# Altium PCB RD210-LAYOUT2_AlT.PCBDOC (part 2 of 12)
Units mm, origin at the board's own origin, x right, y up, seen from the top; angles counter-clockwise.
Board outline 250 x 123 mm, 4 copper layers (TOP, Mid-Layer 1, Mid-Layer 2, BOTTOM), stack 0.711 mm thick; 1043 components, 659 nets, 2786 pads, 1228 vias.
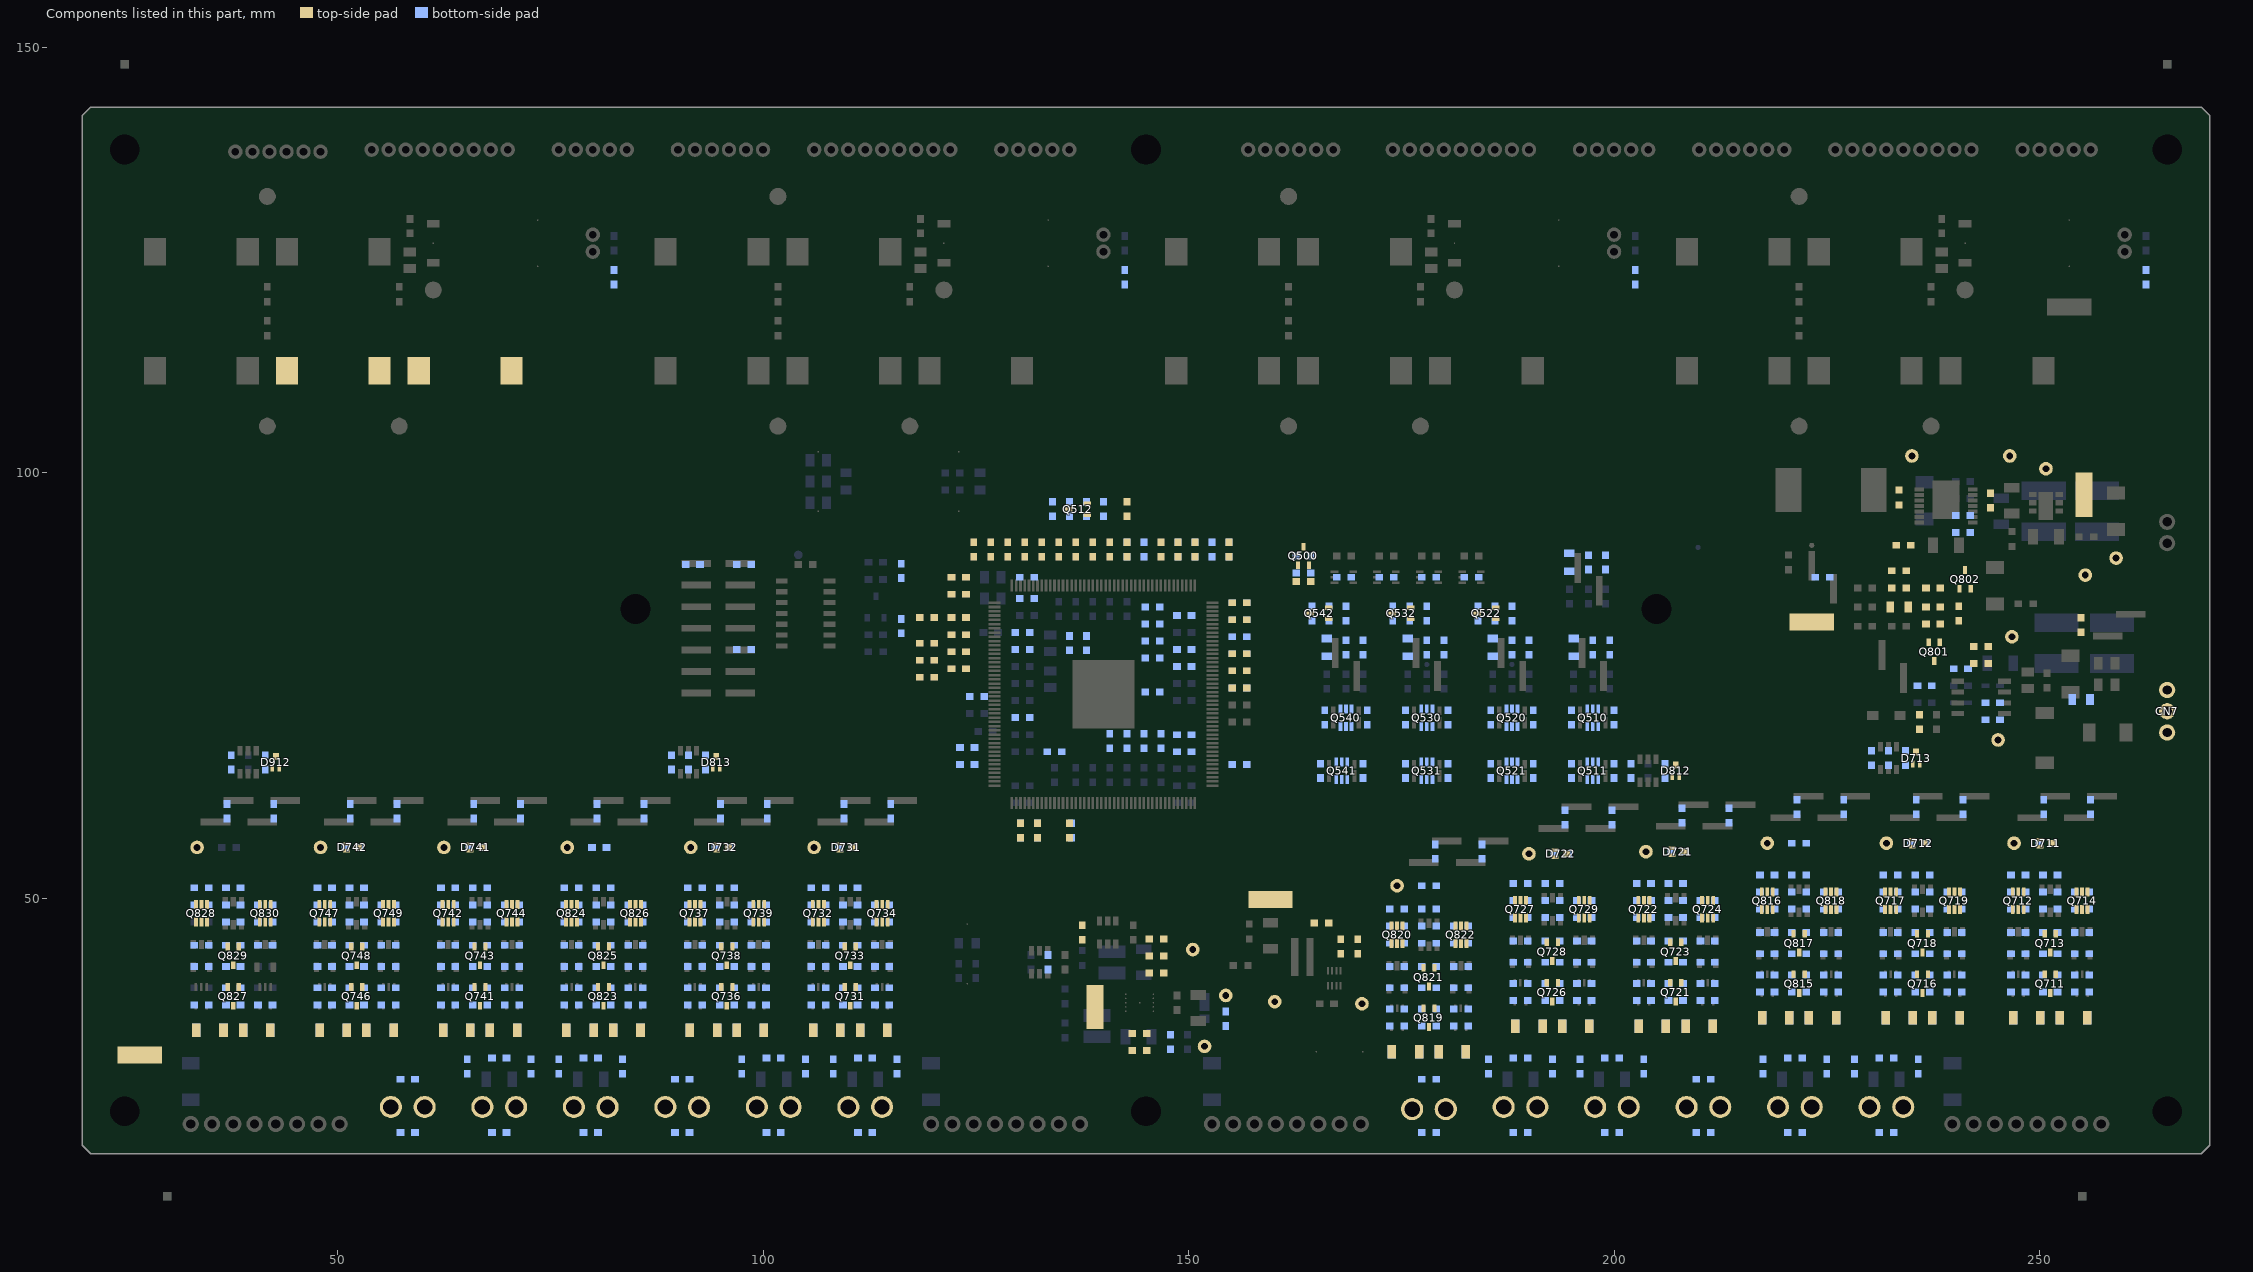
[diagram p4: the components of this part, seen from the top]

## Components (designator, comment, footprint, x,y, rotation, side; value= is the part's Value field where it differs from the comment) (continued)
L820 "S2P_L-12.5x12.1x5.5-PX12.5+18" S2P_L-12.5x12.1x5.5-PX12.5+18 49.5,112 r180 top
L821 "S2P_L-12.5x12.1x5.5-PX12.5+19" S2P_L-12.5x12.1x5.5-PX12.5+19 65,112 r0 top
Q500 "S3P_Q-2.0x1.25x0.9-PX0.65-PY2.1" S3P_Q-2.0x1.25x0.9-PX0.65-PY2.1 163.5,90.25 r0 top
Q510 "_RN1907_" _RN1907_ 197.5,71.25 r0 bottom
Q511 "_RN1907_+1" _RN1907_+1 197.5,65 r0 bottom
Q512 "S3P_Q-2.0x1.25x0.9-PX0.65-PY2.1+6" S3P_Q-2.0x1.25x0.9-PX0.65-PY2.1+6 137,95.75 r90 top
Q520 "_RN1907_+5" _RN1907_+5 188,71.25 r0 bottom
Q521 "_RN1907_+2" _RN1907_+2 188,65 r0 bottom
Q522 "S3P_Q-2.0x1.25x0.9-PX0.65-PY2.1+1" S3P_Q-2.0x1.25x0.9-PX0.65-PY2.1+1 185,83.5 r90 top
Q530 "_RN1907_+7" _RN1907_+7 178,71.25 r0 bottom
Q531 "_RN1907_+6" _RN1907_+6 178,65 r0 bottom
Q532 "S3P_Q-2.0x1.25x0.9-PX0.65-PY2.1+2" S3P_Q-2.0x1.25x0.9-PX0.65-PY2.1+2 175,83.5 r90 top
Q540 "_RN1907_+3" _RN1907_+3 168.5,71.25 r0 bottom
Q541 "_RN1907_+4" _RN1907_+4 168,65 r0 bottom
Q542 "S3P_Q-2.0x1.25x0.9-PX0.65-PY2.1+3" S3P_Q-2.0x1.25x0.9-PX0.65-PY2.1+3 165.375,83.5 r90 top
Q711 "S3P_Q-2.0x1.25x0.9-PX0.65-PY2.1+7" S3P_Q-2.0x1.25x0.9-PX0.65-PY2.1+7 251.25,40 r180 top
Q712 "_RN4907_+22" _RN4907_+22 247.5,49.75 r0 top
Q713 "S3P_Q-2.0x1.25x0.9-PX0.65-PY2.1+8" S3P_Q-2.0x1.25x0.9-PX0.65-PY2.1+8 251.25,44.75 r180 top
Q714 "_RN4907_" _RN4907_ 255,49.75 r0 top
Q716 "S3P_Q-2.0x1.25x0.9-PX0.65-PY2.1+9" S3P_Q-2.0x1.25x0.9-PX0.65-PY2.1+9 236.25,40 r180 top
Q717 "_RN4907_+1" _RN4907_+1 232.5,49.75 r0 top
Q718 "S3P_Q-2.0x1.25x0.9-PX0.65-PY2.1+10" S3P_Q-2.0x1.25x0.9-PX0.65-PY2.1+10 236.25,44.75 r180 top
Q719 "_RN4907_+2" _RN4907_+2 240,49.75 r0 top
Q721 "S3P_Q-2.0x1.25x0.9-PX0.65-PY2.1+11" S3P_Q-2.0x1.25x0.9-PX0.65-PY2.1+11 207.25,39 r180 top
Q722 "_RN4907_+3" _RN4907_+3 203.5,48.75 r0 top
Q723 "S3P_Q-2.0x1.25x0.9-PX0.65-PY2.1+12" S3P_Q-2.0x1.25x0.9-PX0.65-PY2.1+12 207.25,43.75 r180 top
Q724 "_RN4907_+4" _RN4907_+4 211,48.75 r0 top
Q726 "S3P_Q-2.0x1.25x0.9-PX0.65-PY2.1+13" S3P_Q-2.0x1.25x0.9-PX0.65-PY2.1+13 192.75,39 r180 top
Q727 "_RN4907_+5" _RN4907_+5 189,48.75 r0 top
Q728 "S3P_Q-2.0x1.25x0.9-PX0.65-PY2.1+14" S3P_Q-2.0x1.25x0.9-PX0.65-PY2.1+14 192.75,43.75 r180 top
Q729 "_RN4907_+6" _RN4907_+6 196.5,48.75 r0 top
Q731 "S3P_Q-2.0x1.25x0.9-PX0.65-PY2.1+15" S3P_Q-2.0x1.25x0.9-PX0.65-PY2.1+15 110.25,38.5 r180 top
Q732 "_RN4907_+7" _RN4907_+7 106.5,48.25 r0 top
Q733 "S3P_Q-2.0x1.25x0.9-PX0.65-PY2.1+16" S3P_Q-2.0x1.25x0.9-PX0.65-PY2.1+16 110.25,43.25 r180 top
Q734 "_RN4907_+8" _RN4907_+8 114,48.25 r0 top
Q736 "S3P_Q-2.0x1.25x0.9-PX0.65-PY2.1+17" S3P_Q-2.0x1.25x0.9-PX0.65-PY2.1+17 95.75,38.5 r180 top
Q737 "_RN4907_+9" _RN4907_+9 92,48.25 r0 top
Q738 "S3P_Q-2.0x1.25x0.9-PX0.65-PY2.1+18" S3P_Q-2.0x1.25x0.9-PX0.65-PY2.1+18 95.75,43.25 r180 top
Q739 "_RN4907_+10" _RN4907_+10 99.5,48.25 r0 top
Q741 "S3P_Q-2.0x1.25x0.9-PX0.65-PY2.1+19" S3P_Q-2.0x1.25x0.9-PX0.65-PY2.1+19 66.75,38.5 r180 top
Q742 "_RN4907_+11" _RN4907_+11 63,48.25 r0 top
Q743 "S3P_Q-2.0x1.25x0.9-PX0.65-PY2.1+20" S3P_Q-2.0x1.25x0.9-PX0.65-PY2.1+20 66.75,43.25 r180 top
Q744 "_RN4907_+12" _RN4907_+12 70.5,48.25 r0 top
Q746 "S3P_Q-2.0x1.25x0.9-PX0.65-PY2.1+21" S3P_Q-2.0x1.25x0.9-PX0.65-PY2.1+21 52.25,38.5 r180 top
Q747 "_RN4907_+13" _RN4907_+13 48.5,48.25 r0 top
Q748 "S3P_Q-2.0x1.25x0.9-PX0.65-PY2.1+22" S3P_Q-2.0x1.25x0.9-PX0.65-PY2.1+22 52.25,43.25 r180 top
Q749 "_RN4907_+14" _RN4907_+14 56,48.25 r0 top
Q801 "S3P_Q-2.0x1.25x0.9-PX0.65-PY2.1+4" S3P_Q-2.0x1.25x0.9-PX0.65-PY2.1+4 237.625,79 r180 top
Q802 "S3P_Q-2.0x1.25x0.9-PX0.65-PY2.1+5" S3P_Q-2.0x1.25x0.9-PX0.65-PY2.1+5 241.25,87.5 r0 top
Q815 "S3P_Q-2.0x1.25x0.9-PX0.65-PY2.1+23" S3P_Q-2.0x1.25x0.9-PX0.65-PY2.1+23 221.75,40 r180 top
Q816 "_RN4907_+15" _RN4907_+15 218,49.75 r0 top
Q817 "S3P_Q-2.0x1.25x0.9-PX0.65-PY2.1+24" S3P_Q-2.0x1.25x0.9-PX0.65-PY2.1+24 221.75,44.75 r180 top
Q818 "_RN4907_+16" _RN4907_+16 225.5,49.75 r0 top
Q819 "S3P_Q-2.0x1.25x0.9-PX0.65-PY2.1+25" S3P_Q-2.0x1.25x0.9-PX0.65-PY2.1+25 178.25,36 r180 top
Q820 "_RN4907_+23" _RN4907_+23 174.5,45.75 r0 top
Q821 "S3P_Q-2.0x1.25x0.9-PX0.65-PY2.1+26" S3P_Q-2.0x1.25x0.9-PX0.65-PY2.1+26 178.25,40.75 r180 top
Q822 "_RN4907_+17" _RN4907_+17 182,45.75 r0 top
Q823 "S3P_Q-2.0x1.25x0.9-PX0.65-PY2.1+27" S3P_Q-2.0x1.25x0.9-PX0.65-PY2.1+27 81.25,38.5 r180 top
Q824 "_RN4907_+18" _RN4907_+18 77.5,48.25 r0 top
Q825 "S3P_Q-2.0x1.25x0.9-PX0.65-PY2.1+28" S3P_Q-2.0x1.25x0.9-PX0.65-PY2.1+28 81.25,43.25 r180 top
Q826 "_RN4907_+19" _RN4907_+19 85,48.25 r0 top
Q827 "S3P_Q-2.0x1.25x0.9-PX0.65-PY2.1+29" S3P_Q-2.0x1.25x0.9-PX0.65-PY2.1+29 37.75,38.5 r180 top
Q828 "_RN4907_+20" _RN4907_+20 34,48.25 r0 top
Q829 "S3P_Q-2.0x1.25x0.9-PX0.65-PY2.1+30" S3P_Q-2.0x1.25x0.9-PX0.65-PY2.1+30 37.75,43.25 r180 top
Q830 "_RN4907_+21" _RN4907_+21 41.5,48.25 r0 top
R500 "_RS73F1JTTD1002F_+2" _RS73F1JTTD1002F_+2 163.5,90.25 r180 bottom
R501 "_SG73P2ATTD101J_+2" _SG73P2ATTD101J_+2 194.75,89.5 r270 bottom
R502 "_SG73P1JTTD1801F_+2" _SG73P1JTTD1801F_+2 199,89.5 r270 bottom
R503 "_SG73P1JTTD8201F_+2" _SG73P1JTTD8201F_+2 197,89.5 r90 bottom
R504 "_SG73P1JTTD2202F_+5" _SG73P1JTTD2202F_+5 163.5,88.25 r0 bottom
R505 "_SG73P1JTTD2202F_+10" _SG73P1JTTD2202F_+10 163.5,87.25 r180 top
R506 "_RS73G1JTTD1002F_+28" _RS73G1JTTD1002F_+28 144.75,91 r90 bottom
R507 "_RS73G1JTTD1002F_+23" _RS73G1JTTD1002F_+23 134.25,67.25 r180 bottom
R508 "_RS73G1JTTD1002F_+40" _RS73G1JTTD1002F_+40 132.25,58 r90 bottom
R510 "_RS73F1JTTD47R0F_" _RS73F1JTTD47R0F_ 126.75,91 r90 top
R511 "_RS73F1JTTD47R0F_+1" _RS73F1JTTD47R0F_+1 123,85.75 r0 top
R512 "_RS73G1JTTD4701F_+5" _RS73G1JTTD4701F_+5 124.75,91 r90 top
R513 "_RS73G1JTTD4701F_" _RS73G1JTTD4701F_ 119.25,80 r0 top
R514 "_RS73G1JTTD1002F_+27" _RS73G1JTTD1002F_+27 138,80 r270 bottom
R515 "_RS73G1JTTD1002F_+26" _RS73G1JTTD1002F_+26 136,80 r270 bottom
R516 "_RS73G1JTTD4701F_+9" _RS73G1JTTD4701F_+9 200,71.25 r270 bottom
R517 "_RS73G1JTTD1601F_" _RS73G1JTTD1601F_ 195,71.25 r90 bottom
R518 "_RS73G1JTTD1601F_+1" _RS73G1JTTD1601F_+1 200,65 r270 bottom
R519 "_RS73G1JTTD2701F_" _RS73G1JTTD2701F_ 195,65 r90 bottom
R520 "_RS73F1JTTD47R0F_+5" _RS73F1JTTD47R0F_+5 128.75,91 r90 top
R521 "_RS73F1JTTD47R0F_+2" _RS73F1JTTD47R0F_+2 123,83 r0 top
R522 "_RS73G1JTTD4701F_+1" _RS73G1JTTD4701F_+1 123,87.75 r0 top
R523 "_RS73G1JTTD4701F_+2" _RS73G1JTTD4701F_+2 123,79 r0 top
R524 "_RS73G1JTTD1002F_+41" _RS73G1JTTD1002F_+41 130.25,58 r90 bottom
R525 "_RS73G1JTTD1002F_+47" _RS73G1JTTD1002F_+47 146.75,68.5 r270 bottom
R526 "_RS73G1JTTD4701F_+10" _RS73G1JTTD4701F_+10 190.5,71.25 r270 bottom
R527 "_RS73G1JTTD1601F_+2" _RS73G1JTTD1601F_+2 185.5,71.25 r90 bottom
R528 "_RS73G1JTTD1601F_+3" _RS73G1JTTD1601F_+3 190.5,65 r270 bottom
R529 "_RS73G1JTTD2701F_+1" _RS73G1JTTD2701F_+1 185.5,65 r90 bottom
R530 "_RS73F1JTTD47R0F_+6" _RS73F1JTTD47R0F_+6 130.75,91 r90 top
R531 "_RS73F1JTTD47R0F_+4" _RS73F1JTTD47R0F_+4 119.25,83 r0 top
R532 "_RS73G1JTTD4701F_+6" _RS73G1JTTD4701F_+6 138.75,91 r270 top
R533 "_RS73G1JTTD4701F_+3" _RS73G1JTTD4701F_+3 119.25,78 r0 top
R534 "_RS73G1JTTD1002F_" _RS73G1JTTD1002F_ 136,58 r270 top
R535 "_RS73G1JTTD1002F_+1" _RS73G1JTTD1002F_+1 136.25,58 r90 bottom
R536 "_RS73G1JTTD4701F_+11" _RS73G1JTTD4701F_+11 180.5,71.25 r270 bottom
R537 "_RS73G1JTTD1601F_+4" _RS73G1JTTD1601F_+4 175.5,71.25 r90 bottom
R538 "_RS73G1JTTD1601F_+5" _RS73G1JTTD1601F_+5 180.5,65 r270 bottom
R539 "_RS73G1JTTD2701F_+2" _RS73G1JTTD2701F_+2 175.5,65 r90 bottom
R540 "_RS73F1JTTD47R0F_+7" _RS73F1JTTD47R0F_+7 132.75,91 r90 top
R541 "_RS73F1JTTD47R0F_+3" _RS73F1JTTD47R0F_+3 123,81 r0 top
R542 "_RS73G1JTTD4701F_+7" _RS73G1JTTD4701F_+7 140.75,91 r270 top
R543 "_RS73G1JTTD4701F_+4" _RS73G1JTTD4701F_+4 123,77 r0 top
R544 "_RS73G1JTTD1002F_+2" _RS73G1JTTD1002F_+2 156,65.75 r180 bottom
R545 "_RS73G1JTTD1002F_+22" _RS73G1JTTD1002F_+22 149.5,69.25 r180 bottom
R546 "_RS73G1JTTD4701F_+8" _RS73G1JTTD4701F_+8 171,71.25 r270 bottom
R547 "_RS73G1JTTD1601F_+6" _RS73G1JTTD1601F_+6 166,71.25 r90 bottom
R548 "_RS73G1JTTD1601F_+7" _RS73G1JTTD1601F_+7 170.5,65 r270 bottom
R549 "_RS73G1JTTD2701F_+3" _RS73G1JTTD2701F_+3 165.5,65 r90 bottom
R551 "_RS73G1JTTD1002F_+3" _RS73G1JTTD1002F_+3 156,76.75 r180 top
R552 "_RS73G1JTTD1002F_+4" _RS73G1JTTD1002F_+4 156,78.75 r180 top
R553 "_RS73G1JTTD1002F_+5" _RS73G1JTTD1002F_+5 154.75,91 r270 top
R554 "_RS73G1JTTD1002F_+29" _RS73G1JTTD1002F_+29 152.75,91 r90 bottom
R556 "_RS73G1JTTD1002F_+20" _RS73G1JTTD1002F_+20 149.5,77.25 r180 bottom
R557 "_RS73G1JTTD1002F_+18" _RS73G1JTTD1002F_+18 149.5,79.25 r180 bottom
R558 "_RS73G1JTTD1002F_+30" _RS73G1JTTD1002F_+30 154.75,91 r90 bottom
R559 "_RS73G1JTTD1002F_+31" _RS73G1JTTD1002F_+31 150.75,91 r270 top
R562 "_RS73F1JTTD1002F_+8" _RS73F1JTTD1002F_+8 262.5,123 r270 bottom
R563 "_RS73G1JTTD4701F_+14" _RS73G1JTTD4701F_+14 134.75,91 r270 top
R564 "_SG73P2ATTD101J_" _SG73P2ATTD101J_ 195.25,79.5 r270 bottom
R565 "_SG73P1JTTD1801F_" _SG73P1JTTD1801F_ 199.5,79.5 r270 bottom
R566 "_SG73P1JTTD8201F_" _SG73P1JTTD8201F_ 197.5,79.5 r90 bottom
R567 "_SG73P1JTTD2202F_+1" _SG73P1JTTD2202F_+1 140,95.75 r90 bottom
R568 "_SG73P1JTTD2202F_+2" _SG73P1JTTD2202F_+2 138,95.75 r90 bottom
R569 "_RS73F1JTTD1002F_" _RS73F1JTTD1002F_ 136,95.75 r270 bottom
R572 "_RS73F1JTTD1002F_+5" _RS73F1JTTD1002F_+5 202.5,123 r270 bottom
R573 "_RS73G1JTTD4701F_+12" _RS73G1JTTD4701F_+12 136.75,91 r270 top
R574 "_SG73P2ATTD101J_+3" _SG73P2ATTD101J_+3 185.75,79.5 r270 bottom
R575 "_SG73P1JTTD1801F_+3" _SG73P1JTTD1801F_+3 190,79.5 r270 bottom
R576 "_SG73P1JTTD8201F_+3" _SG73P1JTTD8201F_+3 188,79.5 r90 bottom
R577 "_SG73P1JTTD2202F_+6" _SG73P1JTTD2202F_+6 188,83.5 r270 bottom
R578 "_SG73P1JTTD2202F_+7" _SG73P1JTTD2202F_+7 186,83.5 r270 bottom
R579 "_RS73F1JTTD1002F_+3" _RS73F1JTTD1002F_+3 184,83.5 r270 bottom
R582 "_RS73F1JTTD1002F_+6" _RS73F1JTTD1002F_+6 142.5,123 r270 bottom
R583 "_RS73G1JTTD4701F_+15" _RS73G1JTTD4701F_+15 119.25,76 r180 top
R584 "_SG73P2ATTD101J_+4" _SG73P2ATTD101J_+4 175.75,79.5 r90 bottom
R585 "_SG73P1JTTD1801F_+4" _SG73P1JTTD1801F_+4 180,79.5 r270 bottom
R586 "_SG73P1JTTD8201F_+4" _SG73P1JTTD8201F_+4 178,79.5 r90 bottom
R587 "_SG73P1JTTD2202F_+8" _SG73P1JTTD2202F_+8 178,83.5 r90 bottom
R588 "_SG73P1JTTD2202F_+9" _SG73P1JTTD2202F_+9 176,83.5 r270 bottom
R589 "_RS73G1JTTD1002F_+42" _RS73G1JTTD1002F_+42 174,83.5 r270 bottom
R592 "_RS73F1JTTD1002F_+7" _RS73F1JTTD1002F_+7 82.5,123 r270 bottom
R593 "_RS73G1JTTD4701F_+13" _RS73G1JTTD4701F_+13 134,95.75 r90 bottom
R594 "_SG73P2ATTD101J_+1" _SG73P2ATTD101J_+1 166.25,79.5 r270 bottom
R595 "_SG73P1JTTD1801F_+1" _SG73P1JTTD1801F_+1 170.5,79.5 r270 bottom
R596 "_SG73P1JTTD8201F_+1" _SG73P1JTTD8201F_+1 168.5,79.5 r90 bottom
R597 "_SG73P1JTTD2202F_+3" _SG73P1JTTD2202F_+3 168.5,83.5 r270 bottom
R598 "_SG73P1JTTD2202F_+4" _SG73P1JTTD2202F_+4 166.5,83.5 r270 bottom
R599 "_RS73F1JTTD1002F_+1" _RS73F1JTTD1002F_+1 164.5,83.5 r270 bottom
R600 "_RS73G1JTTD1002F_+38" _RS73G1JTTD1002F_+38 156,78.75 r0 bottom
R601 "_RS73G1JTTD1002F_+19" _RS73G1JTTD1002F_+19 145.75,78.25 r180 bottom
R602 "_RS73G1JTTD1002F_+37" _RS73G1JTTD1002F_+37 156,80.75 r0 bottom
R603 "_RS73G1JTTD1002F_+17" _RS73G1JTTD1002F_+17 145.75,80.25 r180 bottom
R604 "_RS73G1JTTD1002F_+6" _RS73G1JTTD1002F_+6 142.75,91 r270 top
R605 "_RS73G1JTTD1002F_+7" _RS73G1JTTD1002F_+7 142.75,95.75 r90 top
R606 "_RS73G1JTTD1002F_+32" _RS73G1JTTD1002F_+32 150.75,91 r90 bottom
R607 "_RS73G1JTTD1002F_+8" _RS73G1JTTD1002F_+8 148.75,91 r270 top
R608 "_RS73G1JTTD1002F_+33" _RS73G1JTTD1002F_+33 148.75,91 r90 bottom
R609 "_RS73G1JTTD1002F_+34" _RS73G1JTTD1002F_+34 146.75,91 r270 top
R613 "_RS73G1JTTD1002F_+25" _RS73G1JTTD1002F_+25 125.125,73.75 r180 bottom
R614 "_RS73G1JTTD1002F_+24" _RS73G1JTTD1002F_+24 130.5,71.25 r180 bottom
R618 "_RS73G1JTTD1002F_+9" _RS73G1JTTD1002F_+9 130.25,58 r270 top
R620 "_RS73G1JTTD1002F_+10" _RS73G1JTTD1002F_+10 132.25,58 r270 top
R623 "_RS73G1JTTD1002F_+44" _RS73G1JTTD1002F_+44 140.75,68.5 r270 bottom
R624 "_RS73G1JTTD1002F_+39" _RS73G1JTTD1002F_+39 144.75,68.5 r270 bottom
R631 "_RS73G1JTTD5602F_" _RS73G1JTTD5602F_ 149.5,67.25 r0 bottom
R632 "_RS73G1JTTD2201F_+2" _RS73G1JTTD2201F_+2 137.5,46 r90 top
R633 "_RS73G1JTTD2201F_+1" _RS73G1JTTD2201F_+1 133.5,42.5 r90 bottom
R634 "_RS73G1JTTD1002F_+14" _RS73G1JTTD1002F_+14 145.75,84.25 r180 bottom
R635 "_RK73H1JTTD473F_+2" _RK73H1JTTD473F_+2 178.25,87.75 r180 bottom
R636 "_RK73H1JTTD473F_+3" _RK73H1JTTD473F_+3 168.25,87.75 r180 bottom
R637 "_RK73H1JTTD473F_+1" _RK73H1JTTD473F_+1 173.25,87.75 r180 bottom
R638 "_RS73G1JTTD1002F_+46" _RS73G1JTTD1002F_+46 156,74.75 r0 bottom
R639 "_RS73G1JTTD1002F_+21" _RS73G1JTTD1002F_+21 145.75,74.25 r180 bottom
R640 "_RS73G1JTTD1002F_+36" _RS73G1JTTD1002F_+36 156,82.75 r0 bottom
R641 "_RS73G1JTTD1002F_+16" _RS73G1JTTD1002F_+16 145.75,82.25 r180 bottom
R642 "_RS73G1JTTD1002F_+11" _RS73G1JTTD1002F_+11 156,82.75 r180 top
R643 "_RS73G1JTTD1002F_+15" _RS73G1JTTD1002F_+15 149.5,83.25 r180 bottom
R644 "_RS73G1JTTD1002F_+35" _RS73G1JTTD1002F_+35 156,84.75 r0 bottom
R645 "_RS73G1JTTD1002F_+12" _RS73G1JTTD1002F_+12 156,84.75 r180 top
R646 "_RS73G1JTTD1002F_+43" _RS73G1JTTD1002F_+43 142.75,91 r90 bottom
R647 "_RS73G1JTTD1002F_+45" _RS73G1JTTD1002F_+45 142.75,68.5 r270 bottom
R648 "_RK73H1JTTD473F_" _RK73H1JTTD473F_ 183.25,87.75 r180 bottom
R655 "_RS73G1JTTD5602F_+1" _RS73G1JTTD5602F_+1 156,74.75 r0 top
R656 "_RS73F1JTTD4701F_" _RS73F1JTTD4701F_ 97.75,79.25 r0 bottom
R657 "_RS73F1JTTD4701F_+1" _RS73F1JTTD4701F_+1 97.75,89.25 r0 bottom
R658 "_RS73F1JTTD4701F_+2" _RS73F1JTTD4701F_+2 91.75,89.25 r180 bottom
R659 "_RS73F1JTTD39R0F_" _RS73F1JTTD39R0F_ 124,67.75 r0 bottom
R660 "_RS73F1JTTD3000F_" _RS73F1JTTD3000F_ 116.25,82 r90 bottom
R661 "_RS73G1JTTD1001F_+1" _RS73G1JTTD1001F_+1 116.25,88.5 r270 bottom
R662 "_RK73B1JTTD1R0J_" _RK73B1JTTD1R0J_ 130.5,79.25 r180 bottom
R663 "_RK73B1JTTD1R0J_+3" _RK73B1JTTD1R0J_+3 131,85.25 r180 bottom
R664 "_RK73B1JTTD1R0J_+1" _RK73B1JTTD1R0J_+1 130.5,81.25 r180 bottom
R665 "_RK73B1JTTD1R0J_+2" _RK73B1JTTD1R0J_+2 131,87.75 r180 bottom
R669 "_RS73G1JTTD2201F_" _RS73G1JTTD2201F_ 124,65.75 r180 bottom
R670 "_RS73F1JTTD2403D_" _RS73F1JTTD2403D_ 165.625,47.125 r180 top
R671 "_RS73F1JTTD2402D_" _RS73F1JTTD2402D_ 167.875,44.375 r90 top
R672 "_RS73G1JTTD1001F_" _RS73G1JTTD1001F_ 144.25,32.125 r0 top
R673 "_RS73F1JTTD3602D_" _RS73F1JTTD3602D_ 169.875,44.375 r270 top
R674 "_RS73G1JTTD1002F_+13" _RS73G1JTTD1002F_+13 154.375,35.875 r90 bottom
R675 "_RS73F1JTTD7501D_" _RS73F1JTTD7501D_ 146.25,43.25 r180 top
R676 "_RS73F1JTTD3303D_" _RS73F1JTTD3303D_ 146.25,45.25 r0 top
R677 "_RS73F1JTTD7502D_" _RS73F1JTTD7502D_ 146.25,41.25 r0 top
R678 "_RS73F1JTTD2003D_+1" _RS73F1JTTD2003D_+1 147.875,33.125 r90 bottom
R679 "_RS73F1JTTD2003D_" _RS73F1JTTD2003D_ 144.25,34.125 r0 top
R701 "_RK73Z1JTTD_" _RK73Z1JTTD_ 250.5,60.75 r270 bottom
R702 "_RK73Z1JTTD_+2" _RK73Z1JTTD_+2 208,59.75 r270 bottom
R703 "_RK73Z1JTTD_+12" _RK73Z1JTTD_+12 109.5,60.25 r270 bottom
R704 "_RK73Z1JTTD_+14" _RK73Z1JTTD_+14 66,60.25 r270 bottom
R706 "_RK73H1JTTD47R0F_+12" _RK73H1JTTD47R0F_+12 230.25,66.5 r90 bottom
R707 "_RK73H1JTTD47R0F_+38" _RK73H1JTTD47R0F_+38 202,65 r90 bottom
R708 "_RK73H1JTTD47R0F_+29" _RK73H1JTTD47R0F_+29 89.25,66 r90 bottom
R709 "_RK73H1JTTD47R0F_+37" _RK73H1JTTD47R0F_+37 37.5,66 r90 bottom
R711 "_RK73Z1JTTD_+4" _RK73Z1JTTD_+4 235.5,60.75 r270 bottom
R712 "_RK73Z1JTTD_+9" _RK73Z1JTTD_+9 194.25,59.5 r270 bottom
R713 "_RK73Z1JTTD_+16" _RK73Z1JTTD_+16 95,60.25 r270 bottom
R714 "_RK73Z1JTTD_+20" _RK73Z1JTTD_+20 51.5,60.25 r270 bottom
R716 "_RK73Z1JTTD_+7" _RK73Z1JTTD_+7 221.5,60.75 r270 bottom
R717 "_RK73Z1JTTD_+11" _RK73Z1JTTD_+11 179,55.5 r270 bottom
R718 "_RK73Z1JTTD_+18" _RK73Z1JTTD_+18 80.5,60.25 r270 bottom
R719 "_RK73Z1JTTD_+23" _RK73Z1JTTD_+23 37,60.25 r270 bottom
R720 "_RK73H1JTTD1001F_" _RK73H1JTTD1001F_ 247.5,46 r180 bottom
R721 "_RK73H1JTTD1001F_+4" _RK73H1JTTD1001F_+4 255,46 r180 bottom
R722 "_RK73H1JTTD2202F_" _RK73H1JTTD2202F_ 251.25,41 r0 bottom
R723 "_RK73H1JTTD2202F_+1" _RK73H1JTTD2202F_+1 251.25,46 r0 bottom
R724 "_RK73H1JTTD1001F_+1" _RK73H1JTTD1001F_+1 251.25,39 r180 bottom
R725 "_RK73H1JTTD1001F_+3" _RK73H1JTTD1001F_+3 251.25,43.5 r180 bottom
R726 "_RK73H1JTTD1001F_+2" _RK73H1JTTD1001F_+2 247.5,43.5 r0 bottom
R727 "_RK73H1JTTD1001F_+5" _RK73H1JTTD1001F_+5 255,48.75 r180 bottom
R728 "_RK73H1JTTD2701F_" _RK73H1JTTD2701F_ 247.5,50.75 r0 bottom
R729 "_RK73H1JTTD2701F_+1" _RK73H1JTTD2701F_+1 251.25,48.75 r0 bottom
R730 "_RK73B2BTTD100J_+21" _RK73B2BTTD100J_+21 254,36 r180 top
R731 "_RK73B2BTTD100J_+18" _RK73B2BTTD100J_+18 248.5,36 r180 bottom
R732 "_RK73B2BTTD100J_+23" _RK73B2BTTD100J_+23 254,36 r0 bottom
R733 "_RK73B2BTTD100J_+20" _RK73B2BTTD100J_+20 248.5,36 r180 top
R734 "_RK73B1JTTD103J_+1" _RK73B1JTTD103J_+1 247.5,52.75 r180 bottom
R735 "_RK73B1JTTD103J_+2" _RK73B1JTTD103J_+2 255,50.75 r0 bottom
R736 "_RK73H1JTTD47R0F_+2" _RK73H1JTTD47R0F_+2 251.25,50.75 r0 bottom
R737 "_RK73H1JTTD47R0F_+1" _RK73H1JTTD47R0F_+1 251.25,52.75 r180 bottom
R738 "_RK73H1JTTD47R0F_" _RK73H1JTTD47R0F_ 228.25,30.25 r270 bottom
R739 "_RK73H1JTTD10R0F_" _RK73H1JTTD10R0F_ 235.75,30.25 r270 bottom
R740 "_RK73H1JTTD1001F_+7" _RK73H1JTTD1001F_+7 203.5,45 r180 bottom
R741 "_RK73H1JTTD1001F_+11" _RK73H1JTTD1001F_+11 211,45 r180 bottom
R742 "_RK73H1JTTD2202F_+2" _RK73H1JTTD2202F_+2 207.25,40 r0 bottom
R743 "_RK73H1JTTD2202F_+3" _RK73H1JTTD2202F_+3 207.25,45 r0 bottom
R744 "_RK73H1JTTD1001F_+6" _RK73H1JTTD1001F_+6 207.25,38 r180 bottom
R745 "_RK73H1JTTD1001F_+9" _RK73H1JTTD1001F_+9 207.25,42.5 r180 bottom
R746 "_RK73H1JTTD1001F_+8" _RK73H1JTTD1001F_+8 203.5,42.5 r0 bottom
R747 "_RK73H1JTTD1001F_+10" _RK73H1JTTD1001F_+10 211,47.75 r180 bottom
R748 "_RK73H1JTTD2701F_+3" _RK73H1JTTD2701F_+3 203.5,49.75 r0 bottom
R749 "_RK73H1JTTD2701F_+2" _RK73H1JTTD2701F_+2 207.25,47.75 r0 bottom
R750 "_RK73B2BTTD100J_" _RK73B2BTTD100J_ 210,35 r180 top
R751 "_RK73B2BTTD100J_+19" _RK73B2BTTD100J_+19 204.5,35 r180 bottom
R752 "_RK73B2BTTD100J_+22" _RK73B2BTTD100J_+22 210,35 r0 bottom
R753 "_RK73B2BTTD100J_+1" _RK73B2BTTD100J_+1 204.5,35 r180 top
R754 "_RK73B1JTTD103J_+3" _RK73B1JTTD103J_+3 203.5,51.75 r180 bottom
R755 "_RK73B1JTTD103J_+4" _RK73B1JTTD103J_+4 211,49.75 r0 bottom
R756 "_RK73H1JTTD47R0F_+5" _RK73H1JTTD47R0F_+5 207.25,49.75 r0 bottom
R757 "_RK73H1JTTD47R0F_+4" _RK73H1JTTD47R0F_+4 207.25,51.75 r180 bottom
R758 "_RK73H1JTTD47R0F_+3" _RK73H1JTTD47R0F_+3 196,30.25 r270 bottom
R759 "_RK73H1JTTD10R0F_+1" _RK73H1JTTD10R0F_+1 203.5,30.25 r270 bottom
R760 "_RK73H1JTTD1001F_+37" _RK73H1JTTD1001F_+37 106.5,44.5 r180 bottom
R761 "_RK73H1JTTD1001F_+40" _RK73H1JTTD1001F_+40 114,44.5 r180 bottom
R762 "_RK73H1JTTD2202F_+12" _RK73H1JTTD2202F_+12 110.25,39.5 r0 bottom
R763 "_RK73H1JTTD2202F_+13" _RK73H1JTTD2202F_+13 110.25,44.5 r0 bottom
R764 "_RK73H1JTTD1001F_+36" _RK73H1JTTD1001F_+36 110.25,37.5 r180 bottom
R765 "_RK73H1JTTD1001F_+39" _RK73H1JTTD1001F_+39 110.25,42 r180 bottom
R766 "_RK73H1JTTD1001F_+38" _RK73H1JTTD1001F_+38 106.5,42 r0 bottom
R767 "_RK73H1JTTD1001F_+41" _RK73H1JTTD1001F_+41 114,47.25 r180 bottom
R768 "_RK73H1JTTD2701F_+12" _RK73H1JTTD2701F_+12 106.5,49.25 r0 bottom
R769 "_RK73H1JTTD2701F_+13" _RK73H1JTTD2701F_+13 110.25,47.25 r0 bottom
R770 "_RK73B2BTTD100J_+2" _RK73B2BTTD100J_+2 113,34.5 r180 top
R771 "_RK73B2BTTD100J_+34" _RK73B2BTTD100J_+34 107.5,34.5 r180 bottom
R772 "_RK73B2BTTD100J_+33" _RK73B2BTTD100J_+33 113,34.5 r0 bottom
R773 "_RK73B2BTTD100J_+3" _RK73B2BTTD100J_+3 107.5,34.5 r180 top
R774 "_RK73B1JTTD103J_+12" _RK73B1JTTD103J_+12 106.5,51.25 r180 bottom
R775 "_RK73B1JTTD103J_+13" _RK73B1JTTD103J_+13 114,49.25 r0 bottom
R776 "_RK73H1JTTD47R0F_+19" _RK73H1JTTD47R0F_+19 110.25,49.25 r0 bottom
R777 "_RK73H1JTTD47R0F_+20" _RK73H1JTTD47R0F_+20 110.25,51.25 r180 bottom
R778 "_RK73H1JTTD47R0F_+18" _RK73H1JTTD47R0F_+18 108.25,30.25 r270 bottom
R779 "_RK73H1JTTD10R0F_+6" _RK73H1JTTD10R0F_+6 115.75,30.25 r270 bottom
R780 "_RK73H1JTTD1001F_+43" _RK73H1JTTD1001F_+43 63,44.5 r180 bottom
R781 "_RK73H1JTTD1001F_+46" _RK73H1JTTD1001F_+46 70.5,44.5 r180 bottom
R782 "_RK73H1JTTD2202F_+14" _RK73H1JTTD2202F_+14 66.75,39.5 r0 bottom
R783 "_RK73H1JTTD2202F_+15" _RK73H1JTTD2202F_+15 66.75,44.5 r0 bottom
R784 "_RK73H1JTTD1001F_+42" _RK73H1JTTD1001F_+42 66.75,37.5 r180 bottom
R785 "_RK73H1JTTD1001F_+45" _RK73H1JTTD1001F_+45 66.75,42 r180 bottom
R786 "_RK73H1JTTD1001F_+44" _RK73H1JTTD1001F_+44 63,42 r0 bottom
R787 "_RK73H1JTTD1001F_+47" _RK73H1JTTD1001F_+47 70.5,47.25 r180 bottom
R788 "_RK73H1JTTD2701F_+14" _RK73H1JTTD2701F_+14 63,49.25 r0 bottom
R789 "_RK73H1JTTD2701F_+15" _RK73H1JTTD2701F_+15 66.75,47.25 r0 bottom
R790 "_RK73B2BTTD100J_+4" _RK73B2BTTD100J_+4 69.5,34.5 r180 top
R791 "_RK73B2BTTD100J_+36" _RK73B2BTTD100J_+36 64,34.5 r180 bottom
R792 "_RK73B2BTTD100J_+35" _RK73B2BTTD100J_+35 69.5,34.5 r0 bottom
R793 "_RK73B2BTTD100J_+5" _RK73B2BTTD100J_+5 64,34.5 r180 top
R794 "_RK73B1JTTD103J_+14" _RK73B1JTTD103J_+14 63,51.25 r180 bottom
R795 "_RK73B1JTTD103J_+15" _RK73B1JTTD103J_+15 70.5,49.25 r0 bottom
R796 "_RK73H1JTTD47R0F_+22" _RK73H1JTTD47R0F_+22 66.75,49.25 r0 bottom
R797 "_RK73H1JTTD47R0F_+23" _RK73H1JTTD47R0F_+23 66.75,51.25 r180 bottom
R798 "_RK73H1JTTD47R0F_+21" _RK73H1JTTD47R0F_+21 76,30.25 r270 bottom
R799 "_RK73H1JTTD10R0F_+7" _RK73H1JTTD10R0F_+7 83.5,30.25 r270 bottom
R800 "_RS73F1JTTD2702F_" _RS73F1JTTD2702F_ 236.5,75 r0 bottom
R801 "_RS73F1JTTD1003F_" _RS73F1JTTD1003F_ 244.5,73 r0 bottom
R802 "_SG73P1JTTD2202F_+12" _SG73P1JTTD2202F_+12 237.5,84.25 r0 top
R803 "_SG73P1JTTD2202F_+13" _SG73P1JTTD2202F_+13 237.5,82.25 r0 top
R804 "_RS73F1JTTD1002F_+4" _RS73F1JTTD1002F_+4 235.875,70.75 r270 top
R805 "_RS73F1JTTD1802F_" _RS73F1JTTD1802F_ 243.125,79.625 r180 top
R806 "_RS73F1JTTD1802F_+1" _RS73F1JTTD1802F_+1 244.5,71 r0 bottom
R807 "_SG73P2ATTD100J_" _SG73P2ATTD100J_ 254.875,73.375 r180 bottom
R808 "_RS73F1JTTD1202D_" _RS73F1JTTD1202D_ 240.75,77 r0 bottom
R809 "_RS73F1JTTD1001D_" _RS73F1JTTD1001D_ 243.125,77.625 r180 top
R810 "_SG73P1JTTD2202F_+11" _SG73P1JTTD2202F_+11 237.5,86.5 r0 top
R811 "_SG73P1JTTD2202F_" _SG73P1JTTD2202F_ 240.5,83.5 r90 top
R812 "_RS73F1JTTD4303F_" _RS73F1JTTD4303F_ 244.25,96.75 r270 top
R813 "_SG73P1JTTD1R60F_" _SG73P1JTTD1R60F_ 234,91.5 r180 top
R814 "_RS73F1JTTD6801D_" _RS73F1JTTD6801D_ 241,93 r0 bottom
R815 "_RS73F1JTTD1801D_" _RS73F1JTTD1801D_ 241,95 r180 bottom
R816 "_SG73P2ATTD101J_+5" _SG73P2ATTD101J_+5 233.5,84.25 r0 top
R817 "_SG73P1JTTD1801F_+5" _SG73P1JTTD1801F_+5 233.5,88.5 r0 top
R818 "_SG73P1JTTD8201F_+5" _SG73P1JTTD8201F_+5 233.5,86.5 r180 top
R819 "_RK73G1JTTD10R0D_+1" _RK73G1JTTD10R0D_+1 224.5,87.75 r0 bottom
R820 "_RK73H1JTTD1001F_+13" _RK73H1JTTD1001F_+13 232.5,46 r180 bottom
R821 "_RK73H1JTTD1001F_+16" _RK73H1JTTD1001F_+16 240,46 r180 bottom
R822 "_RK73H1JTTD2202F_+4" _RK73H1JTTD2202F_+4 236.25,41 r0 bottom
R823 "_RK73H1JTTD2202F_+5" _RK73H1JTTD2202F_+5 236.25,46 r0 bottom
R824 "_RK73H1JTTD1001F_+12" _RK73H1JTTD1001F_+12 236.25,39 r180 bottom
R825 "_RK73H1JTTD1001F_+15" _RK73H1JTTD1001F_+15 236.25,43.5 r180 bottom
R826 "_RK73H1JTTD1001F_+14" _RK73H1JTTD1001F_+14 232.5,43.5 r0 bottom
R827 "_RK73H1JTTD1001F_+17" _RK73H1JTTD1001F_+17 240,48.75 r180 bottom
R828 "_RK73H1JTTD2701F_+4" _RK73H1JTTD2701F_+4 232.5,50.75 r0 bottom
R829 "_RK73H1JTTD2701F_+5" _RK73H1JTTD2701F_+5 236.25,48.75 r0 bottom
R830 "_RK73B2BTTD100J_+6" _RK73B2BTTD100J_+6 239,36 r180 top
R831 "_RK73B2BTTD100J_+24" _RK73B2BTTD100J_+24 233.5,36 r180 bottom
R832 "_RK73B2BTTD100J_+25" _RK73B2BTTD100J_+25 239,36 r0 bottom
R833 "_RK73B2BTTD100J_+7" _RK73B2BTTD100J_+7 233.5,36 r180 top
R834 "_RK73B1JTTD103J_+5" _RK73B1JTTD103J_+5 232.5,52.75 r180 bottom
R835 "_RK73B1JTTD103J_+6" _RK73B1JTTD103J_+6 240,50.75 r0 bottom
R836 "_RK73H1JTTD47R0F_+7" _RK73H1JTTD47R0F_+7 236.25,50.75 r0 bottom
R837 "_RK73H1JTTD47R0F_+8" _RK73H1JTTD47R0F_+8 236.25,52.75 r180 bottom
R838 "_RK73H1JTTD47R0F_+6" _RK73H1JTTD47R0F_+6 217.5,30.25 r270 bottom
R839 "_RK73H1JTTD10R0F_+2" _RK73H1JTTD10R0F_+2 225,30.25 r270 bottom
R840 "_RK73H1JTTD1001F_+25" _RK73H1JTTD1001F_+25 189,45 r180 bottom
R841 "_RK73H1JTTD1001F_+29" _RK73H1JTTD1001F_+29 196.5,45 r180 bottom
R842 "_RK73H1JTTD2202F_+8" _RK73H1JTTD2202F_+8 192.75,40 r0 bottom
R843 "_RK73H1JTTD2202F_+9" _RK73H1JTTD2202F_+9 192.75,45 r0 bottom
R844 "_RK73H1JTTD1001F_+24" _RK73H1JTTD1001F_+24 192.75,38 r180 bottom
R845 "_RK73H1JTTD1001F_+27" _RK73H1JTTD1001F_+27 192.75,42.5 r180 bottom
R846 "_RK73H1JTTD1001F_+26" _RK73H1JTTD1001F_+26 189,42.5 r0 bottom
R847 "_RK73H1JTTD1001F_+28" _RK73H1JTTD1001F_+28 196.5,47.75 r180 bottom
R848 "_RK73H1JTTD2701F_+9" _RK73H1JTTD2701F_+9 189,49.75 r0 bottom
R849 "_RK73H1JTTD2701F_+8" _RK73H1JTTD2701F_+8 192.75,47.75 r0 bottom
R850 "_RK73B2BTTD100J_+8" _RK73B2BTTD100J_+8 195.5,35 r180 top
R851 "_RK73B2BTTD100J_+28" _RK73B2BTTD100J_+28 190,35 r180 bottom
R852 "_RK73B2BTTD100J_+30" _RK73B2BTTD100J_+30 195.5,35 r0 bottom
R853 "_RK73B2BTTD100J_+29" _RK73B2BTTD100J_+29 190,35 r180 top
R854 "_RK73B1JTTD103J_+9" _RK73B1JTTD103J_+9 189,51.75 r180 bottom
R855 "_RK73B1JTTD103J_+10" _RK73B1JTTD103J_+10 196.5,49.75 r0 bottom
R856 "_RK73H1JTTD47R0F_+15" _RK73H1JTTD47R0F_+15 192.75,49.75 r0 bottom
R857 "_RK73H1JTTD47R0F_+14" _RK73H1JTTD47R0F_+14 192.75,51.75 r180 bottom
R858 "_RK73H1JTTD47R0F_+13" _RK73H1JTTD47R0F_+13 185.25,30.25 r270 bottom
R859 "_RK73H1JTTD10R0F_+4" _RK73H1JTTD10R0F_+4 192.75,30.25 r270 bottom
R860 "_RK73H1JTTD1001F_+49" _RK73H1JTTD1001F_+49 92,44.5 r180 bottom
R861 "_RK73H1JTTD1001F_+53" _RK73H1JTTD1001F_+53 99.5,44.5 r180 bottom
R862 "_RK73H1JTTD2202F_+16" _RK73H1JTTD2202F_+16 95.75,39.5 r0 bottom
R863 "_RK73H1JTTD2202F_+17" _RK73H1JTTD2202F_+17 95.75,44.5 r0 bottom
R864 "_RK73H1JTTD1001F_+48" _RK73H1JTTD1001F_+48 95.75,37.5 r180 bottom
R865 "_RK73H1JTTD1001F_+51" _RK73H1JTTD1001F_+51 95.75,42 r180 bottom
R866 "_RK73H1JTTD1001F_+50" _RK73H1JTTD1001F_+50 92,42 r0 bottom
R867 "_RK73H1JTTD1001F_+52" _RK73H1JTTD1001F_+52 99.5,47.25 r180 bottom
R868 "_RK73H1JTTD2701F_+16" _RK73H1JTTD2701F_+16 92,49.25 r0 bottom
R869 "_RK73H1JTTD2701F_+17" _RK73H1JTTD2701F_+17 95.75,47.25 r0 bottom
R870 "_RK73B2BTTD100J_+9" _RK73B2BTTD100J_+9 98.5,34.5 r180 top
R871 "_RK73B2BTTD100J_+38" _RK73B2BTTD100J_+38 93,34.5 r180 bottom
R872 "_RK73B2BTTD100J_+37" _RK73B2BTTD100J_+37 98.5,34.5 r0 bottom
R873 "_RK73B2BTTD100J_+10" _RK73B2BTTD100J_+10 93,34.5 r180 top
R874 "_RK73B1JTTD103J_+16" _RK73B1JTTD103J_+16 92,51.25 r180 bottom
R875 "_RK73B1JTTD103J_+17" _RK73B1JTTD103J_+17 99.5,49.25 r0 bottom
R876 "_RK73H1JTTD47R0F_+25" _RK73H1JTTD47R0F_+25 95.75,49.25 r0 bottom
R877 "_RK73H1JTTD47R0F_+26" _RK73H1JTTD47R0F_+26 95.75,51.25 r180 bottom
R878 "_RK73H1JTTD47R0F_+24" _RK73H1JTTD47R0F_+24 97.5,30.25 r270 bottom
R879 "_RK73H1JTTD10R0F_+8" _RK73H1JTTD10R0F_+8 105,30.25 r270 bottom
R880 "_RK73H1JTTD1001F_+62" _RK73H1JTTD1001F_+62 48.5,44.5 r180 bottom
R881 "_RK73H1JTTD1001F_+64" _RK73H1JTTD1001F_+64 56,44.5 r180 bottom
R882 "_RK73H1JTTD2202F_+20" _RK73H1JTTD2202F_+20 52.25,39.5 r0 bottom
R883 "_RK73H1JTTD2202F_+21" _RK73H1JTTD2202F_+21 52.25,44.5 r0 bottom
R884 "_RK73H1JTTD1001F_+60" _RK73H1JTTD1001F_+60 52.25,37.5 r180 bottom
R885 "_RK73H1JTTD1001F_+61" _RK73H1JTTD1001F_+61 52.25,42 r180 bottom
R886 "_RK73H1JTTD1001F_+63" _RK73H1JTTD1001F_+63 48.5,42 r0 bottom
R887 "_RK73H1JTTD1001F_+65" _RK73H1JTTD1001F_+65 56,47.25 r180 bottom
R888 "_RK73H1JTTD2701F_+20" _RK73H1JTTD2701F_+20 48.5,49.25 r0 bottom
R889 "_RK73H1JTTD2701F_+21" _RK73H1JTTD2701F_+21 52.25,47.25 r0 bottom
R890 "_RK73B2BTTD100J_+11" _RK73B2BTTD100J_+11 55,34.5 r180 top
R891 "_RK73B2BTTD100J_+41" _RK73B2BTTD100J_+41 49.5,34.5 r180 bottom
R892 "_RK73B2BTTD100J_+42" _RK73B2BTTD100J_+42 55,34.5 r0 bottom
R893 "_RK73B2BTTD100J_+12" _RK73B2BTTD100J_+12 49.5,34.5 r180 top
R894 "_RK73B1JTTD103J_+20" _RK73B1JTTD103J_+20 48.5,51.25 r180 bottom
R895 "_RK73B1JTTD103J_+21" _RK73B1JTTD103J_+21 56,49.25 r0 bottom
R896 "_RK73H1JTTD47R0F_+32" _RK73H1JTTD47R0F_+32 52.25,49.25 r0 bottom
R897 "_RK73H1JTTD47R0F_+33" _RK73H1JTTD47R0F_+33 52.25,51.25 r180 bottom
R898 "_RK73H1JTTD47R0F_+31" _RK73H1JTTD47R0F_+31 65.25,30.25 r270 bottom
R899 "_RK73H1JTTD10R0F_+10" _RK73H1JTTD10R0F_+10 72.75,30.25 r270 bottom
R900 "_RK73G1JTTD10R0D_" _RK73G1JTTD10R0D_ 254.875,82.125 r90 top
R901 "_RK73Z1JTTD_+1" _RK73Z1JTTD_+1 256,60.75 r270 bottom
R902 "_RK73Z1JTTD_+3" _RK73Z1JTTD_+3 213.5,59.75 r270 bottom
R903 "_RK73Z1JTTD_+13" _RK73Z1JTTD_+13 115,60.25 r270 bottom
R904 "_RK73Z1JTTD_+15" _RK73Z1JTTD_+15 71.5,60.25 r270 bottom
R906 "_RK73H1JTTD47R0F_+11" _RK73H1JTTD47R0F_+11 234.25,66.5 r90 bottom
R907 "_RK73H1JTTD47R0F_+39" _RK73H1JTTD47R0F_+39 206,65 r90 bottom
R908 "_RK73H1JTTD47R0F_+30" _RK73H1JTTD47R0F_+30 93.25,66 r90 bottom
R909 "_RK73H1JTTD47R0F_+36" _RK73H1JTTD47R0F_+36 41.5,66 r270 bottom
R911 "_RK73Z1JTTD_+5" _RK73Z1JTTD_+5 241,60.75 r270 bottom
R912 "_RK73Z1JTTD_+8" _RK73Z1JTTD_+8 199.75,59.5 r270 bottom
R913 "_RK73Z1JTTD_+17" _RK73Z1JTTD_+17 100.5,60.25 r270 bottom
R914 "_RK73Z1JTTD_+21" _RK73Z1JTTD_+21 57,60.25 r270 bottom
R916 "_RK73Z1JTTD_+6" _RK73Z1JTTD_+6 227,60.75 r270 bottom
R917 "_RK73Z1JTTD_+10" _RK73Z1JTTD_+10 184.5,55.5 r270 bottom
R918 "_RK73Z1JTTD_+19" _RK73Z1JTTD_+19 86,60.25 r270 bottom
R919 "_RK73Z1JTTD_+22" _RK73Z1JTTD_+22 42.5,60.25 r270 bottom
R920 "_RK73H1JTTD1001F_+19" _RK73H1JTTD1001F_+19 218,46 r180 bottom
R921 "_RK73H1JTTD1001F_+23" _RK73H1JTTD1001F_+23 225.5,46 r180 bottom
R922 "_RK73H1JTTD2202F_+6" _RK73H1JTTD2202F_+6 221.75,41 r0 bottom
R923 "_RK73H1JTTD2202F_+7" _RK73H1JTTD2202F_+7 221.75,46 r0 bottom
R924 "_RK73H1JTTD1001F_+18" _RK73H1JTTD1001F_+18 221.75,39 r180 bottom
R925 "_RK73H1JTTD1001F_+21" _RK73H1JTTD1001F_+21 221.75,43.5 r180 bottom
R926 "_RK73H1JTTD1001F_+20" _RK73H1JTTD1001F_+20 218,43.5 r0 bottom
R927 "_RK73H1JTTD1001F_+22" _RK73H1JTTD1001F_+22 225.5,48.75 r180 bottom
R928 "_RK73H1JTTD2701F_+6" _RK73H1JTTD2701F_+6 218,50.75 r0 bottom
R929 "_RK73H1JTTD2701F_+7" _RK73H1JTTD2701F_+7 221.75,48.75 r0 bottom
R930 "_RK73B2BTTD100J_+13" _RK73B2BTTD100J_+13 224.5,36 r180 top
R931 "_RK73B2BTTD100J_+26" _RK73B2BTTD100J_+26 219,36 r180 bottom
R932 "_RK73B2BTTD100J_+27" _RK73B2BTTD100J_+27 224.5,36 r0 bottom
R933 "_RK73B2BTTD100J_+14" _RK73B2BTTD100J_+14 219,36 r180 top
R934 "_RK73B1JTTD103J_+7" _RK73B1JTTD103J_+7 218,52.75 r180 bottom
R935 "_RK73B1JTTD103J_+8" _RK73B1JTTD103J_+8 225.5,50.75 r0 bottom
R936 "_RK73H1JTTD47R0F_+9" _RK73H1JTTD47R0F_+9 221.75,50.75 r0 bottom
R937 "_RK73H1JTTD47R0F_+10" _RK73H1JTTD47R0F_+10 221.75,52.75 r180 bottom
R939 "_RK73H1JTTD10R0F_+3" _RK73H1JTTD10R0F_+3 210.5,28.75 r180 bottom
R940 "_RK73H1JTTD1001F_+31" _RK73H1JTTD1001F_+31 174.5,42 r180 bottom
R941 "_RK73H1JTTD1001F_+34" _RK73H1JTTD1001F_+34 182,42 r180 bottom
R942 "_RK73H1JTTD2202F_+10" _RK73H1JTTD2202F_+10 178.25,37 r0 bottom
R943 "_RK73H1JTTD2202F_+11" _RK73H1JTTD2202F_+11 178.25,42 r0 bottom
R944 "_RK73H1JTTD1001F_+30" _RK73H1JTTD1001F_+30 178.25,35 r180 bottom
R945 "_RK73H1JTTD1001F_+33" _RK73H1JTTD1001F_+33 178.25,39.5 r180 bottom
R946 "_RK73H1JTTD1001F_+32" _RK73H1JTTD1001F_+32 174.5,39.5 r0 bottom
R947 "_RK73H1JTTD1001F_+35" _RK73H1JTTD1001F_+35 182,44.75 r180 bottom
R948 "_RK73H1JTTD2701F_+10" _RK73H1JTTD2701F_+10 174.5,46.75 r0 bottom
R949 "_RK73H1JTTD2701F_+11" _RK73H1JTTD2701F_+11 178.25,44.75 r0 bottom
R950 "_RK73B2BTTD100J_+46" _RK73B2BTTD100J_+46 181,32 r180 top
R951 "_RK73B2BTTD100J_+31" _RK73B2BTTD100J_+31 175.5,32 r180 bottom
R952 "_RK73B2BTTD100J_+32" _RK73B2BTTD100J_+32 181,32 r0 bottom
R953 "_RK73B2BTTD100J_+47" _RK73B2BTTD100J_+47 175.5,32 r180 top
R954 "_RK73B1JTTD103J_" _RK73B1JTTD103J_ 174.5,48.75 r180 bottom
R955 "_RK73B1JTTD103J_+11" _RK73B1JTTD103J_+11 182,46.75 r0 bottom
R956 "_RK73H1JTTD47R0F_+16" _RK73H1JTTD47R0F_+16 178.25,46.75 r0 bottom
R957 "_RK73H1JTTD47R0F_+17" _RK73H1JTTD47R0F_+17 178.25,48.75 r180 bottom
R959 "_RK73H1JTTD10R0F_+5" _RK73H1JTTD10R0F_+5 178.25,28.75 r180 bottom
R960 "_RK73H1JTTD1001F_+55" _RK73H1JTTD1001F_+55 77.5,44.5 r180 bottom
R961 "_RK73H1JTTD1001F_+58" _RK73H1JTTD1001F_+58 85,44.5 r180 bottom
R962 "_RK73H1JTTD2202F_+18" _RK73H1JTTD2202F_+18 81.25,39.5 r0 bottom
R963 "_RK73H1JTTD2202F_+19" _RK73H1JTTD2202F_+19 81.25,44.5 r0 bottom
R964 "_RK73H1JTTD1001F_+54" _RK73H1JTTD1001F_+54 81.25,37.5 r180 bottom
R965 "_RK73H1JTTD1001F_+57" _RK73H1JTTD1001F_+57 81.25,42 r180 bottom
R966 "_RK73H1JTTD1001F_+56" _RK73H1JTTD1001F_+56 77.5,42 r0 bottom
R967 "_RK73H1JTTD1001F_+59" _RK73H1JTTD1001F_+59 85,47.25 r180 bottom
R968 "_RK73H1JTTD2701F_+18" _RK73H1JTTD2701F_+18 77.5,49.25 r0 bottom
R969 "_RK73H1JTTD2701F_+19" _RK73H1JTTD2701F_+19 81.25,47.25 r0 bottom
R970 "_RK73B2BTTD100J_+15" _RK73B2BTTD100J_+15 84,34.5 r180 top
R971 "_RK73B2BTTD100J_+39" _RK73B2BTTD100J_+39 78.5,34.5 r180 bottom
R972 "_RK73B2BTTD100J_+40" _RK73B2BTTD100J_+40 84,34.5 r0 bottom
R973 "_RK73B2BTTD100J_+16" _RK73B2BTTD100J_+16 78.5,34.5 r180 top
R974 "_RK73B1JTTD103J_+18" _RK73B1JTTD103J_+18 77.5,51.25 r180 bottom
R975 "_RK73B1JTTD103J_+19" _RK73B1JTTD103J_+19 85,49.25 r0 bottom
R976 "_RK73H1JTTD47R0F_+27" _RK73H1JTTD47R0F_+27 81.25,49.25 r0 bottom
R977 "_RK73H1JTTD47R0F_+28" _RK73H1JTTD47R0F_+28 81.25,51.25 r180 bottom
R979 "_RK73H1JTTD10R0F_+9" _RK73H1JTTD10R0F_+9 90.5,28.75 r180 bottom
R980 "_RK73H1JTTD1001F_+68" _RK73H1JTTD1001F_+68 34,44.5 r180 bottom
R981 "_RK73H1JTTD1001F_+70" _RK73H1JTTD1001F_+70 41.5,44.5 r180 bottom
R982 "_RK73H1JTTD2202F_+22" _RK73H1JTTD2202F_+22 37.75,39.5 r0 bottom
R983 "_RK73H1JTTD2202F_+23" _RK73H1JTTD2202F_+23 37.75,44.5 r0 bottom
R984 "_RK73H1JTTD1001F_+66" _RK73H1JTTD1001F_+66 37.75,37.5 r180 bottom
R985 "_RK73H1JTTD1001F_+67" _RK73H1JTTD1001F_+67 37.75,42 r180 bottom
R986 "_RK73H1JTTD1001F_+69" _RK73H1JTTD1001F_+69 34,42 r0 bottom
R987 "_RK73H1JTTD1001F_+71" _RK73H1JTTD1001F_+71 41.5,47.25 r180 bottom
R988 "_RK73H1JTTD2701F_+22" _RK73H1JTTD2701F_+22 34,49.25 r0 bottom
R989 "_RK73H1JTTD2701F_+23" _RK73H1JTTD2701F_+23 37.75,47.25 r0 bottom
R990 "_RK73B2BTTD100J_+17" _RK73B2BTTD100J_+17 40.5,34.5 r180 top
R991 "_RK73B2BTTD100J_+45" _RK73B2BTTD100J_+45 35,34.5 r180 bottom
R992 "_RK73B2BTTD100J_+43" _RK73B2BTTD100J_+43 40.5,34.5 r0 bottom
R993 "_RK73B2BTTD100J_+44" _RK73B2BTTD100J_+44 35,34.5 r180 top
R994 "_RK73B1JTTD103J_+22" _RK73B1JTTD103J_+22 34,51.25 r180 bottom
R995 "_RK73B1JTTD103J_+23" _RK73B1JTTD103J_+23 41.5,49.25 r0 bottom
R996 "_RK73H1JTTD47R0F_+34" _RK73H1JTTD47R0F_+34 37.75,49.25 r0 bottom
R997 "_RK73H1JTTD47R0F_+35" _RK73H1JTTD47R0F_+35 37.75,51.25 r180 bottom
R999 "_RK73H1JTTD10R0F_+11" _RK73H1JTTD10R0F_+11 58.25,28.75 r180 bottom
TP801 "_HW-1-S_+1" _HW-1-S_+1 26.75,31.625 r0 top
TP802 "_HW-1-S_+2" _HW-1-S_+2 255.25,97.45 r90 top
TP803 "_TSW-101-07-G-S_" _TSW-101-07-G-S_ 259,90 r0 top
TP804 "_HW-1-S_+3" _HW-1-S_+3 159.625,49.875 r0 top
TP805 "_HW-1-S_+4" _HW-1-S_+4 223.23,82.5 r0 top
TP806 "_HW-1-S_+5" _HW-1-S_+5 139,37.25 r90 top
? "_CGA3E2X7R1H104K080AA_+56" _CGA3E2X7R1H104K080AA_+56 51.75,56 r0 bottom

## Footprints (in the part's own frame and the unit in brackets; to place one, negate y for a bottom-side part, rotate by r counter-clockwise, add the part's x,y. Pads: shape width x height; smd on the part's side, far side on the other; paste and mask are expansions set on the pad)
_1SS362FV_ [mm] "KC00080BKP"
  rect 0.4x0.8 smd paste-0.8 mask+0: 1(-0.4,-0.7) 2(0.4,-0.7)
  rect 0.7x0.8 smd paste-0.8 mask+0: 3(0,0.7)
_1SS362FV_+1 [mm] "KC00080BKP"
  rect 0.4x0.8 smd paste-0.8 mask+0: 1(-0.4,-0.7) 2(0.4,-0.7)
  rect 0.7x0.8 smd paste-0.8 mask+0: 3(0,0.7)
_1SS362FV_+2 [mm] "KC00080BKP"
  rect 0.4x0.8 smd paste-0.8 mask+0: 1(-0.4,-0.7) 2(0.4,-0.7)
  rect 0.7x0.8 smd paste-0.8 mask+0: 3(0,0.7)
_1SS362FV_+3 [mm] "KC00080BKP"
  rect 0.4x0.8 smd paste-0.8 mask+0: 1(-0.4,-0.7) 2(0.4,-0.7)
  rect 0.7x0.8 smd paste-0.8 mask+0: 3(0,0.7)
_1SS362FV_+4 [mm] "KC00080BKP"
  rect 0.4x0.8 smd paste-0.8 mask+0: 1(-0.4,-0.7) 2(0.4,-0.7)
  rect 0.7x0.8 smd paste-0.8 mask+0: 3(0,0.7)
_1SS362FV_+5 [mm] "KC00080BKP"
  rect 0.4x0.8 smd paste-0.8 mask+0: 1(-0.4,-0.7) 2(0.4,-0.7)
  rect 0.7x0.8 smd paste-0.8 mask+0: 3(0,0.7)
_1SS362FV_+6 [mm] "KC00080BKP"
  rect 0.4x0.8 smd paste-0.8 mask+0: 1(-0.4,-0.7) 2(0.4,-0.7)
  rect 0.7x0.8 smd paste-0.8 mask+0: 3(0,0.7)
_1SS362FV_+7 [mm] "KC00080BKP"
  rect 0.4x0.8 smd paste-0.8 mask+0: 1(-0.4,-0.7) 2(0.4,-0.7)
  rect 0.7x0.8 smd paste-0.8 mask+0: 3(0,0.7)
_1SS362FV_+8 [mm] "KC00080BKP"
  rect 0.4x0.8 smd paste-0.8 mask+0: 1(-0.4,-0.7) 2(0.4,-0.7)
  rect 0.7x0.8 smd paste-0.8 mask+0: 3(0,0.7)
_1SS362FV_+9 [mm] "KC00080BKP"
  rect 0.4x0.8 smd paste-0.8 mask+0: 1(-0.4,-0.7) 2(0.4,-0.7)
  rect 0.7x0.8 smd paste-0.8 mask+0: 3(0,0.7)
_1SS362FV_+10 [mm] "KC00080BKP"
  rect 0.4x0.8 smd paste-0.8 mask+0: 1(-0.4,-0.7) 2(0.4,-0.7)
  rect 0.7x0.8 smd paste-0.8 mask+0: 3(0,0.7)
_1SS362FV_+11 [mm] "KC00080BKP"
  rect 0.4x0.8 smd paste-0.8 mask+0: 1(-0.4,-0.7) 2(0.4,-0.7)
  rect 0.7x0.8 smd paste-0.8 mask+0: 3(0,0.7)
_B2P-VH_ [mm] "KC00080BKP"
  round 2.6 hole 1.8 paste-2.7 mask+0: 1(-1.98,0) 2(1.98,0)
_B3B-XH-A_ [mm] "KC00080BKP"
  round 1.9 hole 1.1 paste-2 mask+0: 1(2.5,0) 2(0,0) 3(-2.5,0)
_CEU3E2X7R1H223K080AE_ [mm] "KC00080BKP"
  rect 0.85x0.8 smd paste-0.85 mask+0: 1(-0.875,0) 2(0.875,0)
_CGA3E2C0G1H472J080AA_ [mm] "KC00080BKP"
  rect 0.9x0.8 smd paste-0.9 mask+0: 1(0.85,0) 2(-0.85,0)
_CGA3E2C0G1H472J080AA_+1 [mm] "KC00080BKP"
  rect 0.9x0.8 smd paste-0.9 mask+0: 1(0.85,0) 2(-0.85,0)
_CGA3E2C0G1H472J080AA_+2 [mm] "KC00080BKP"
  rect 0.9x0.8 smd paste-0.9 mask+0: 1(0.85,0) 2(-0.85,0)
_CGA3E2C0G1H472J080AA_+3 [mm] "KC00080BKP"
  rect 0.9x0.8 smd paste-0.9 mask+0: 1(0.85,0) 2(-0.85,0)
_CGA3E2C0G1H472J080AA_+4 [mm] "KC00080BKP"
  rect 0.9x0.8 smd paste-0.9 mask+0: 1(0.85,0) 2(-0.85,0)
_CGA3E2C0G1H472J080AA_+5 [mm] "KC00080BKP"
  rect 0.9x0.8 smd paste-0.9 mask+0: 1(0.85,0) 2(-0.85,0)
_CGA3E2C0G1H472J080AA_+6 [mm] "KC00080BKP"
  rect 0.9x0.8 smd paste-0.9 mask+0: 1(0.85,0) 2(-0.85,0)
_CGA3E2C0G1H472J080AA_+7 [mm] "KC00080BKP"
  rect 0.9x0.8 smd paste-0.9 mask+0: 1(0.85,0) 2(-0.85,0)
_CGA3E2C0G1H472J080AA_+8 [mm] "KC00080BKP"
  rect 0.9x0.8 smd paste-0.9 mask+0: 1(0.85,0) 2(-0.85,0)
_CGA3E2C0G1H472J080AA_+9 [mm] "KC00080BKP"
  rect 0.9x0.8 smd paste-0.9 mask+0: 1(0.85,0) 2(-0.85,0)
_CGA3E2C0G1H472J080AA_+10 [mm] "KC00080BKP"
  rect 0.9x0.8 smd paste-0.9 mask+0: 1(0.85,0) 2(-0.85,0)
_CGA3E2C0G1H472J080AA_+11 [mm] "KC00080BKP"
  rect 0.9x0.8 smd paste-0.9 mask+0: 1(0.85,0) 2(-0.85,0)
_CGA3E2C0G1H472J080AA_+12 [mm] "KC00080BKP"
  rect 0.9x0.8 smd paste-0.9 mask+0: 1(0.85,0) 2(-0.85,0)
_CGA3E2C0G1H472J080AA_+13 [mm] "KC00080BKP"
  rect 0.9x0.8 smd paste-0.9 mask+0: 1(0.85,0) 2(-0.85,0)
_CGA3E2C0G1H472J080AA_+14 [mm] "KC00080BKP"
  rect 0.9x0.8 smd paste-0.9 mask+0: 1(0.85,0) 2(-0.85,0)
_CGA3E2C0G1H472J080AA_+15 [mm] "KC00080BKP"
  rect 0.9x0.8 smd paste-0.9 mask+0: 1(0.85,0) 2(-0.85,0)
_CGA3E2C0G1H472J080AA_+16 [mm] "KC00080BKP"
  rect 0.9x0.8 smd paste-0.9 mask+0: 1(0.85,0) 2(-0.85,0)
_CGA3E2C0G1H472J080AA_+17 [mm] "KC00080BKP"
  rect 0.9x0.8 smd paste-0.9 mask+0: 1(0.85,0) 2(-0.85,0)
_CGA3E2C0G1H472J080AA_+18 [mm] "KC00080BKP"
  rect 0.9x0.8 smd paste-0.9 mask+0: 1(0.85,0) 2(-0.85,0)
_CGA3E2C0G1H472J080AA_+19 [mm] "KC00080BKP"
  rect 0.9x0.8 smd paste-0.9 mask+0: 1(0.85,0) 2(-0.85,0)
_CGA3E2C0G1H472J080AA_+20 [mm] "KC00080BKP"
  rect 0.9x0.8 smd paste-0.9 mask+0: 1(0.85,0) 2(-0.85,0)
_CGA3E2C0G1H472J080AA_+21 [mm] "KC00080BKP"
  rect 0.9x0.8 smd paste-0.9 mask+0: 1(0.85,0) 2(-0.85,0)
_CGA3E2C0G1H472J080AA_+22 [mm] "KC00080BKP"
  rect 0.9x0.8 smd paste-0.9 mask+0: 1(0.85,0) 2(-0.85,0)
_CGA3E2C0G1H472J080AA_+23 [mm] "KC00080BKP"
  rect 0.9x0.8 smd paste-0.9 mask+0: 1(0.85,0) 2(-0.85,0)
_CGA3E2C0G1H472J080AA_+24 [mm] "KC00080BKP"
  rect 0.9x0.8 smd paste-0.9 mask+0: 1(0.85,0) 2(-0.85,0)
_CGA3E2C0G1H472J080AA_+25 [mm] "KC00080BKP"
  rect 0.9x0.8 smd paste-0.9 mask+0: 1(0.85,0) 2(-0.85,0)
_CGA3E2C0G1H472J080AA_+26 [mm] "KC00080BKP"
  rect 0.9x0.8 smd paste-0.9 mask+0: 1(0.85,0) 2(-0.85,0)
_CGA3E2C0G1H472J080AA_+27 [mm] "KC00080BKP"
  rect 0.9x0.8 smd paste-0.9 mask+0: 1(0.85,0) 2(-0.85,0)
_CGA3E2C0G1H472J080AA_+28 [mm] "KC00080BKP"
  rect 0.9x0.8 smd paste-0.9 mask+0: 1(0.85,0) 2(-0.85,0)
_CGA3E2C0G1H472J080AA_+29 [mm] "KC00080BKP"
  rect 0.9x0.8 smd paste-0.9 mask+0: 1(0.85,0) 2(-0.85,0)
_CGA3E2C0G1H472J080AA_+30 [mm] "KC00080BKP"
  rect 0.9x0.8 smd paste-0.9 mask+0: 1(0.85,0) 2(-0.85,0)
_CGA3E2C0G1H472J080AA_+31 [mm] "KC00080BKP"
  rect 0.9x0.8 smd paste-0.9 mask+0: 1(0.85,0) 2(-0.85,0)
_CGA3E2C0G1H472J080AA_+32 [mm] "KC00080BKP"
  rect 0.9x0.8 smd paste-0.9 mask+0: 1(0.85,0) 2(-0.85,0)
_CGA3E2C0G1H472J080AA_+33 [mm] "KC00080BKP"
  rect 0.9x0.8 smd paste-0.9 mask+0: 1(0.85,0) 2(-0.85,0)
_CGA3E2C0G1H472J080AA_+34 [mm] "KC00080BKP"
  rect 0.9x0.8 smd paste-0.9 mask+0: 1(0.85,0) 2(-0.85,0)
_CGA3E2C0G1H472J080AA_+35 [mm] "KC00080BKP"
  rect 0.9x0.8 smd paste-0.9 mask+0: 1(0.85,0) 2(-0.85,0)
_CGA3E2C0G1H472J080AA_+36 [mm] "KC00080BKP"
  rect 0.9x0.8 smd paste-0.9 mask+0: 1(0.85,0) 2(-0.85,0)
_CGA3E2C0G1H472J080AA_+37 [mm] "KC00080BKP"
  rect 0.9x0.8 smd paste-0.9 mask+0: 1(0.85,0) 2(-0.85,0)
_CGA3E2C0G1H472J080AA_+38 [mm] "KC00080BKP"
  rect 0.9x0.8 smd paste-0.9 mask+0: 1(0.85,0) 2(-0.85,0)
_CGA3E2C0G1H472J080AA_+39 [mm] "KC00080BKP"
  rect 0.9x0.8 smd paste-0.9 mask+0: 1(0.85,0) 2(-0.85,0)
_CGA3E2C0G1H472J080AA_+40 [mm] "KC00080BKP"
  rect 0.9x0.8 smd paste-0.9 mask+0: 1(0.85,0) 2(-0.85,0)
_CGA3E2C0G1H472J080AA_+41 [mm] "KC00080BKP"
  rect 0.9x0.8 smd paste-0.9 mask+0: 1(0.85,0) 2(-0.85,0)
_CGA3E2C0G1H472J080AA_+42 [mm] "KC00080BKP"
  rect 0.9x0.8 smd paste-0.9 mask+0: 1(0.85,0) 2(-0.85,0)
_CGA3E2C0G1H472J080AA_+43 [mm] "KC00080BKP"
  rect 0.9x0.8 smd paste-0.9 mask+0: 1(0.85,0) 2(-0.85,0)
_CGA3E2X7R1H104K080AA_ [mm] "KC00080BKP"
  rect 0.9x0.8 smd paste-0.9 mask+0: 1(0.85,0) 2(-0.85,0)
_CGA3E2X7R1H104K080AA_+1 [mm] "KC00080BKP"
  rect 0.9x0.8 smd paste-0.9 mask+0: 1(0.85,0) 2(-0.85,0)
_CGA3E2X7R1H104K080AA_+2 [mm] "KC00080BKP"
  rect 0.9x0.8 smd paste-0.9 mask+0: 1(0.85,0) 2(-0.85,0)
_CGA3E2X7R1H104K080AA_+3 [mm] "KC00080BKP"
  rect 0.9x0.8 smd paste-0.9 mask+0: 1(0.85,0) 2(-0.85,0)
_CGA3E2X7R1H104K080AA_+4 [mm] "KC00080BKP"
  rect 0.9x0.8 smd paste-0.9 mask+0: 1(0.85,0) 2(-0.85,0)
_CGA3E2X7R1H104K080AA_+5 [mm] "KC00080BKP"
  rect 0.9x0.8 smd paste-0.9 mask+0: 1(0.85,0) 2(-0.85,0)
_CGA3E2X7R1H104K080AA_+6 [mm] "KC00080BKP"
  rect 0.9x0.8 smd paste-0.9 mask+0: 1(0.85,0) 2(-0.85,0)
_CGA3E2X7R1H104K080AA_+7 [mm] "KC00080BKP"
  rect 0.9x0.8 smd paste-0.9 mask+0: 1(0.85,0) 2(-0.85,0)
_CGA3E2X7R1H104K080AA_+8 [mm] "KC00080BKP"
  rect 0.9x0.8 smd paste-0.9 mask+0: 1(0.85,0) 2(-0.85,0)
_CGA3E2X7R1H104K080AA_+9 [mm] "KC00080BKP"
  rect 0.9x0.8 smd paste-0.9 mask+0: 1(0.85,0) 2(-0.85,0)
_CGA3E2X7R1H104K080AA_+10 [mm] "KC00080BKP"
  rect 0.9x0.8 smd paste-0.9 mask+0: 1(0.85,0) 2(-0.85,0)
_CGA3E2X7R1H104K080AA_+11 [mm] "KC00080BKP"
  rect 0.9x0.8 smd paste-0.9 mask+0: 1(0.85,0) 2(-0.85,0)
_CGA3E2X7R1H104K080AA_+12 [mm] "KC00080BKP"
  rect 0.9x0.8 smd paste-0.9 mask+0: 1(0.85,0) 2(-0.85,0)
_CGA3E2X7R1H104K080AA_+13 [mm] "KC00080BKP"
  rect 0.9x0.8 smd paste-0.9 mask+0: 1(0.85,0) 2(-0.85,0)
_CGA3E2X7R1H104K080AA_+14 [mm] "KC00080BKP"
  rect 0.9x0.8 smd paste-0.9 mask+0: 1(0.85,0) 2(-0.85,0)
_CGA3E2X7R1H104K080AA_+15 [mm] "KC00080BKP"
  rect 0.9x0.8 smd paste-0.9 mask+0: 1(0.85,0) 2(-0.85,0)
_CGA3E2X7R1H104K080AA_+16 [mm] "KC00080BKP"
  rect 0.9x0.8 smd paste-0.9 mask+0: 1(0.85,0) 2(-0.85,0)
_CGA3E2X7R1H104K080AA_+17 [mm] "KC00080BKP"
  rect 0.9x0.8 smd paste-0.9 mask+0: 1(0.85,0) 2(-0.85,0)
_CGA3E2X7R1H104K080AA_+18 [mm] "KC00080BKP"
  rect 0.9x0.8 smd paste-0.9 mask+0: 1(0.85,0) 2(-0.85,0)
_CGA3E2X7R1H104K080AA_+19 [mm] "KC00080BKP"
  rect 0.9x0.8 smd paste-0.9 mask+0: 1(0.85,0) 2(-0.85,0)
_CGA3E2X7R1H104K080AA_+20 [mm] "KC00080BKP"
  rect 0.9x0.8 smd paste-0.9 mask+0: 1(0.85,0) 2(-0.85,0)
_CGA3E2X7R1H104K080AA_+21 [mm] "KC00080BKP"
  rect 0.9x0.8 smd paste-0.9 mask+0: 1(0.85,0) 2(-0.85,0)
_CGA3E2X7R1H104K080AA_+22 [mm] "KC00080BKP"
  rect 0.9x0.8 smd paste-0.9 mask+0: 1(0.85,0) 2(-0.85,0)
_CGA3E2X7R1H104K080AA_+23 [mm] "KC00080BKP"
  rect 0.9x0.8 smd paste-0.9 mask+0: 1(0.85,0) 2(-0.85,0)
_CGA3E2X7R1H104K080AA_+24 [mm] "KC00080BKP"
  rect 0.9x0.8 smd paste-0.9 mask+0: 1(0.85,0) 2(-0.85,0)
_CGA3E2X7R1H104K080AA_+25 [mm] "KC00080BKP"
  rect 0.9x0.8 smd paste-0.9 mask+0: 1(0.85,0) 2(-0.85,0)
_CGA3E2X7R1H104K080AA_+26 [mm] "KC00080BKP"
  rect 0.9x0.8 smd paste-0.9 mask+0: 1(0.85,0) 2(-0.85,0)
_CGA3E2X7R1H104K080AA_+27 [mm] "KC00080BKP"
  rect 0.9x0.8 smd paste-0.9 mask+0: 1(0.85,0) 2(-0.85,0)
_CGA3E2X7R1H104K080AA_+28 [mm] "KC00080BKP"
  rect 0.9x0.8 smd paste-0.9 mask+0: 1(0.85,0) 2(-0.85,0)
_CGA3E2X7R1H104K080AA_+29 [mm] "KC00080BKP"
  rect 0.9x0.8 smd paste-0.9 mask+0: 1(0.85,0) 2(-0.85,0)
_CGA3E2X7R1H104K080AA_+30 [mm] "KC00080BKP"
  rect 0.9x0.8 smd paste-0.9 mask+0: 1(0.85,0) 2(-0.85,0)
_CGA3E2X7R1H104K080AA_+31 [mm] "KC00080BKP"
  rect 0.9x0.8 smd paste-0.9 mask+0: 1(0.85,0) 2(-0.85,0)
_CGA3E2X7R1H104K080AA_+32 [mm] "KC00080BKP"
  rect 0.9x0.8 smd paste-0.9 mask+0: 1(0.85,0) 2(-0.85,0)
_CGA3E2X7R1H104K080AA_+33 [mm] "KC00080BKP"
  rect 0.9x0.8 smd paste-0.9 mask+0: 1(0.85,0) 2(-0.85,0)
_CGA3E2X7R1H104K080AA_+34 [mm] "KC00080BKP"
  rect 0.9x0.8 smd paste-0.9 mask+0: 1(0.85,0) 2(-0.85,0)
_CGA3E2X7R1H104K080AA_+35 [mm] "KC00080BKP"
  rect 0.9x0.8 smd paste-0.9 mask+0: 1(0.85,0) 2(-0.85,0)
_CGA3E2X7R1H104K080AA_+36 [mm] "KC00080BKP"
  rect 0.9x0.8 smd paste-0.9 mask+0: 1(0.85,0) 2(-0.85,0)
_CGA3E2X7R1H104K080AA_+37 [mm] "KC00080BKP"
  rect 0.9x0.8 smd paste-0.9 mask+0: 1(0.85,0) 2(-0.85,0)
_CGA3E2X7R1H104K080AA_+38 [mm] "KC00080BKP"
  rect 0.9x0.8 smd paste-0.9 mask+0: 1(0.85,0) 2(-0.85,0)
_CGA3E2X7R1H104K080AA_+39 [mm] "KC00080BKP"
  rect 0.9x0.8 smd paste-0.9 mask+0: 1(0.85,0) 2(-0.85,0)
_CGA3E2X7R1H104K080AA_+40 [mm] "KC00080BKP"
  rect 0.9x0.8 smd paste-0.9 mask+0: 1(0.85,0) 2(-0.85,0)
_CGA3E2X7R1H104K080AA_+41 [mm] "KC00080BKP"
  rect 0.9x0.8 smd paste-0.9 mask+0: 1(0.85,0) 2(-0.85,0)
_CGA3E2X7R1H104K080AA_+42 [mm] "KC00080BKP"
  rect 0.9x0.8 smd paste-0.9 mask+0: 1(0.85,0) 2(-0.85,0)
_CGA3E2X7R1H104K080AA_+43 [mm] "KC00080BKP"
  rect 0.9x0.8 smd paste-0.9 mask+0: 1(0.85,0) 2(-0.85,0)
_CGA3E2X7R1H104K080AA_+44 [mm] "KC00080BKP"
  rect 0.9x0.8 smd paste-0.9 mask+0: 1(0.85,0) 2(-0.85,0)
_CGA3E2X7R1H104K080AA_+45 [mm] "KC00080BKP"
  rect 0.9x0.8 smd paste-0.9 mask+0: 1(0.85,0) 2(-0.85,0)
_CGA3E2X7R1H104K080AA_+46 [mm] "KC00080BKP"
  rect 0.9x0.8 smd paste-0.9 mask+0: 1(0.85,0) 2(-0.85,0)
_CGA3E2X7R1H104K080AA_+47 [mm] "KC00080BKP"
  rect 0.9x0.8 smd paste-0.9 mask+0: 1(0.85,0) 2(-0.85,0)
_CGA3E2X7R1H104K080AA_+48 [mm] "KC00080BKP"
  rect 0.9x0.8 smd paste-0.9 mask+0: 1(0.85,0) 2(-0.85,0)
_CGA3E2X7R1H104K080AA_+49 [mm] "KC00080BKP"
  rect 0.9x0.8 smd paste-0.9 mask+0: 1(0.85,0) 2(-0.85,0)
_CGA3E2X7R1H104K080AA_+50 [mm] "KC00080BKP"
  rect 0.9x0.8 smd paste-0.9 mask+0: 1(0.85,0) 2(-0.85,0)
_CGA3E2X7R1H104K080AA_+51 [mm] "KC00080BKP"
  rect 0.9x0.8 smd paste-0.9 mask+0: 1(0.85,0) 2(-0.85,0)
_CGA3E2X7R1H104K080AA_+52 [mm] "KC00080BKP"
  rect 0.9x0.8 smd paste-0.9 mask+0: 1(0.85,0) 2(-0.85,0)
_CGA3E2X7R1H104K080AA_+53 [mm] "KC00080BKP"
  rect 0.9x0.8 smd paste-0.9 mask+0: 1(0.85,0) 2(-0.85,0)
_CGA3E2X7R1H104K080AA_+54 [mm] "KC00080BKP"
  rect 0.9x0.8 smd paste-0.9 mask+0: 1(0.85,0) 2(-0.85,0)
_CGA3E2X7R1H104K080AA_+55 [mm] "KC00080BKP"
  rect 0.9x0.8 smd paste-0.9 mask+0: 1(0.85,0) 2(-0.85,0)
_CGA3E2X7R1H104K080AA_+56 [mm] "KC00080BKP"
  rect 0.9x0.8 smd paste-0.9 mask+0: 1(0.85,0) 2(-0.85,0)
